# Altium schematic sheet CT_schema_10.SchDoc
size 147 x 119 mm
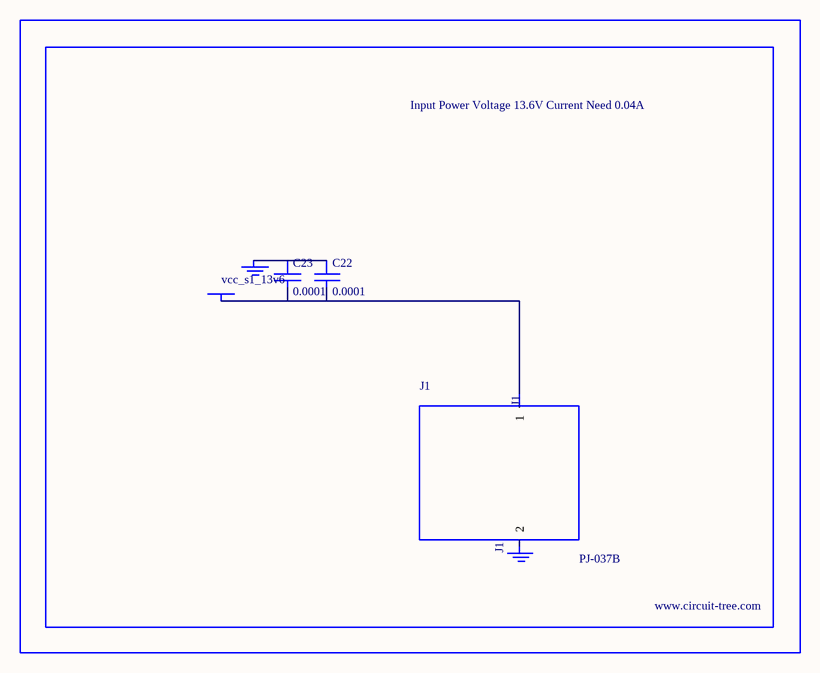
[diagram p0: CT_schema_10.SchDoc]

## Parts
BORDER9  (no value)
C22  0.0001  [EXV-9H]
C23  0.0001  [EXV-9H]
GND_INSTANCE_9_0  (no value)
GND_INSTANCE_9_1  (no value)
J1  PJ-037B  [PJ-037B_PACKAGE]
POWER_INSTANCE_9_0  vcc_s1_13v6

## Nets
NetC22_1: C22.1 C23.1 GND_INSTANCE_9_0.0(GND)
NetC22_2: C22.2 C23.2 J1.1 POWER_INSTANCE_9_0.0(PWR)

Not connected (* = marked no-connect by the designer): GND_INSTANCE_9_1 0(GND); J1 2

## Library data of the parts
BORDER9 = BORDER_PAGE9
C22 C23 = EDK107M035A9HAA
GND_INSTANCE_9_0 GND_INSTANCE_9_1 = GND
POWER_INSTANCE_9_0 = PWR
